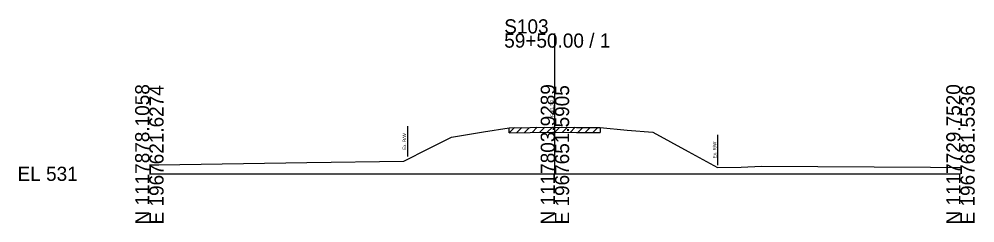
# Model space of a CAD drawing. Extents: x -26 to 163, y -10 to 24018.
# Drawn here: x -25.7 to 162.8, y 8990.3 to 9030.5 of the extents above; entities that cross this region are included whole.
import ezdxf

# ---------------------------------------------------------------- set-up
doc = ezdxf.new("R2010")
doc.units = 0
for name, color, linetype in [('RD_GPK_XS_Cell', 7, 'Continuous'), ('RD_XS_ExGround', 7, 'Continuous'), ('RD_XS_ExPaveRet', 7, 'Continuous'), ('RD_XS_ExRW', 7, 'Continuous'), ('RD_XS_TX_Elev_EX', 7, 'Continuous')]:
    doc.layers.add(name, color=color, linetype=linetype)

msp = doc.modelspace()

# ---------------------------------------------------------------- linework, layer by layer
at = {"layer": 'RD_GPK_XS_Cell'}
for p, q in [((80, 9000), (80, 9027.69)), ((0, 9000), (80, 9000)), ((80, 9000), (160, 9000))]:
    msp.add_line(p, q, dxfattribs=at)
at = {"layer": 'RD_XS_ExGround'}
msp.add_lwpolyline([(0, 9001.79), (1.89, 9001.78), (31.04, 9002.26), (50.17, 9002.52), (55.1, 9004.99), (59.59, 9007.22), (65.94, 9008.28), (70.99, 9009.1), (75.13, 9009.16), (79.57, 9009.23), (80, 9009.22), (84.24, 9009.16), (88.91, 9009.12), (94.28, 9008.62), (99.29, 9008.21), (106.27, 9004.38), (112.07, 9001.21), (116.71, 9001.29), (120.77, 9001.49), (154.11, 9001.29), (160, 9001.22)], dxfattribs=at)
at = {"layer": 'RD_XS_ExPaveRet'}
for p, q in [((70.99, 9008.1), (72, 9009.12)), ((70.99, 9008.1), (70.99, 9009.1)), ((70.99, 9008.1), (75.13, 9008.16)), ((72.49, 9008.13), (73.5, 9009.14)), ((73.99, 9008.15), (75, 9009.16)), ((75.13, 9008.16), (79.57, 9008.23)), ((75.49, 9008.17), (76.5, 9009.18)), ((76.99, 9008.19), (78, 9009.21)), ((78.49, 9008.21), (79.5, 9009.23)), ((79.57, 9008.23), (80, 9008.22)), ((79.99, 9008.22), (80.97, 9009.21)), ((80, 9008.22), (84.24, 9008.16)), ((81.49, 9008.2), (82.47, 9009.19)), ((82.99, 9008.18), (83.97, 9009.17)), ((84.24, 9008.16), (88.91, 9008.12)), ((84.49, 9008.16), (85.48, 9009.15)), ((85.99, 9008.15), (86.98, 9009.14)), ((87.49, 9008.13), (88.48, 9009.12)), ((88.91, 9009.12), (88.91, 9008.12))]:
    msp.add_line(p, q, dxfattribs=at)
at = {"layer": 'RD_XS_ExRW'}
for p, q in [((50.89, 9009.38), (50.89, 9003.38)), ((112.07, 9007.71), (112.07, 9001.71))]:
    msp.add_line(p, q, dxfattribs=at)

# ---------------------------------------------------------------- texts
at = {"layer": 'RD_GPK_XS_Cell'}
for s, p in [('S103', (70, 9027.69)), ('59+50.00 / 1', (70, 9024.89)), ('EL 531', (-26, 8998.6))]:
    msp.add_text(s, height=2.8, dxfattribs=at).set_placement(p)
for s, p in [('N 1117878.1058', (0, 8990)), ('N 1117729.7520', (160, 8990)), ('E 1967621.6274', (2.8, 8990)), ('N 1117803.9289', (80, 8990)), ('E 1967651.5905', (82.8, 8990)), ('E 1967681.5536', (162.8, 8990))]:
    msp.add_text(s, height=2.8, rotation=90, dxfattribs=at).set_placement(p)
at = {"layer": 'RD_XS_ExRW'}
for p in [(50.64, 9004.72), (111.82, 9003.05)]:
    msp.add_text('Ex. R/W ', height=0.65, rotation=90, dxfattribs=at).set_placement(p)
at = {"layer": 'RD_XS_TX_Elev_EX'}
msp.add_text('540.22', height=0.8, rotation=90, dxfattribs=at).set_placement((79.9, 9011.22))

doc.saveas('drawing.dxf')
